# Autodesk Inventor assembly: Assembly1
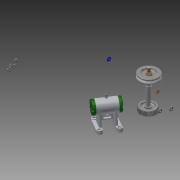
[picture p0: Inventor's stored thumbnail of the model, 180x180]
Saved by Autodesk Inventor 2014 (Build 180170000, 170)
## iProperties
Created: 2015-11
Part Number: Assembly1
Document SubType Name: Assembly
Designer: user
Author: user
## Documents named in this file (16)
- C:\Users\user\Desktop\451110V1011\Assembly1.iam
- C:\Users\user\Desktop\451110V1011\451110V1011본체.ipt
- C:\Users\user\Desktop\451110V1011\커버.ipt
- C:\Users\user\Desktop\451110V1011\베어링 15 x 32 x 9.ipt
- C:\Users\user\Desktop\451110V1011\축.ipt
- C:\Users\user\Desktop\451110V1011\오일 실 15 25 7.ipt
- C:\Users\user\Desktop\451110V1011\볼트 M4 x 12.ipt
- C:\Users\user\Desktop\451110V1011\키 3 x 3 x 12.ipt
- C:\Users\user\Desktop\451110V1011\V벨트풀리.ipt
- C:\Users\user\Desktop\451110V1011\스퍼기어.ipt
- C:\Users\user\Desktop\451110V1011\와셔 8x17.ipt
- C:\Users\user\Desktop\451110V1011\스프링와셔 8.ipt
- C:\Users\user\Desktop\451110V1011\너트 M 8.ipt
- C:\Users\user\Desktop\451110V1011\와셔 6x11.5.ipt
- C:\Users\user\Desktop\451110V1011\볼트 M 6 x 8.ipt
- C:\Users\user\Desktop\451110V1011\니플 M 6 x 0.75.ipt
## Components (8 placed, 4 different names)
1. 451110V1011본체:1 — Insert:1, Mate:1, Mate:2, Mate:3, Insert:2, Insert:3, Insert:6
2. KS B 2023 6002 - 15 x 32 x 9:1 — Insert:2
3. KS B 2023 6002 - 15 x 32 x 9:2 — Insert:3
4. ISO 4762 M4 x 12:1
5. ISO 4762 M4 x 12:2
6. ISO 4762 M4 x 12:3
7. ISO 4762 M4 x 12:4
8. V벨트풀리:1 — Insert:14, Mate:7, Insert:15
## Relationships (10: Insert 6, Mate 4)
- Insert:1: 451110V1011본체:1
- Mate:1: 451110V1011본체:1
- Mate:2: 451110V1011본체:1
- Mate:3: 451110V1011본체:1
- Insert:2: 451110V1011본체:1 ↔ KS B 2023 6002 - 15 x 32 x 9:1
- Insert:3: 451110V1011본체:1 ↔ KS B 2023 6002 - 15 x 32 x 9:2
- Insert:6: 451110V1011본체:1
- Insert:14: V벨트풀리:1
- Mate:7: V벨트풀리:1
- Insert:15: V벨트풀리:1
